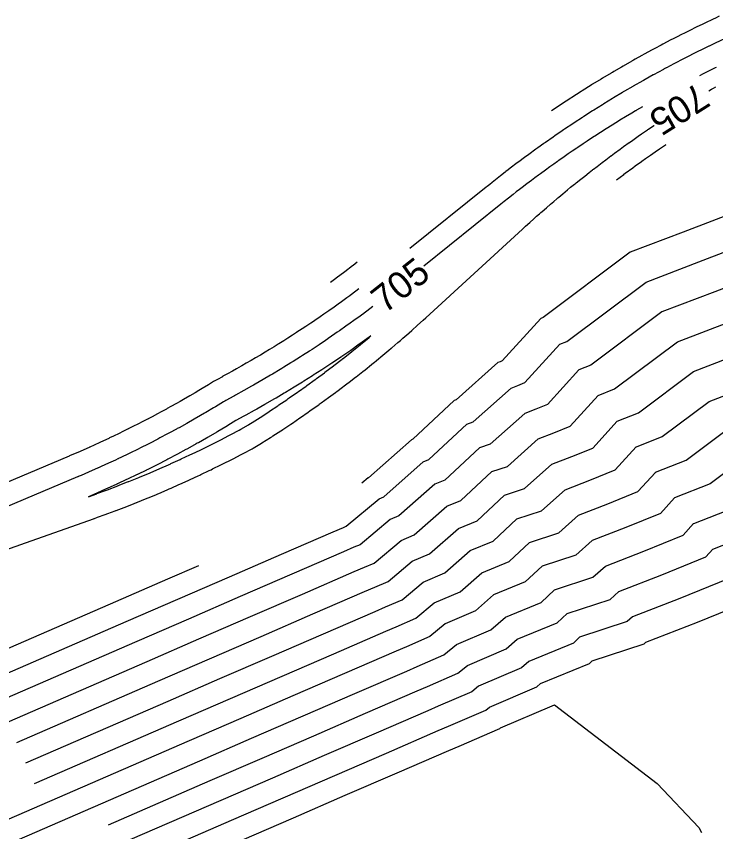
# Model space of a CAD drawing. Extents: x 1487507 to 1489130, y 497211 to 499439.
# Drawn here: x 1487940.5 to 1488002.7, y 498507 to 498579.6 of the extents above; entities that cross this region are included whole.
import ezdxf

# ---------------------------------------------------------------- set-up
doc = ezdxf.new("R2010")
doc.units = 0
for name, color, linetype in [('Prop CMT Ditch DDE', 7, 'Continuous'), ('Prop Drainage Ditch Flow Line', 7, 'Continuous'), ('Prop Drainage Structure Box Number Symbol CELL', 7, 'Continuous')]:
    doc.layers.add(name, color=color, linetype=linetype)

msp = doc.modelspace()

# ---------------------------------------------------------------- linework, layer by layer
at = {"layer": 'Prop CMT Ditch DDE'}
for points in [[(1488003.024, 498579.578), (1488002.689, 498579.423), (1488002.467, 498579.318), (1488001.741, 498578.977), (1488001.609, 498578.913), (1488001.168, 498578.701), (1488001.084, 498578.66), (1488000.798, 498578.521), (1488000.589, 498578.417), (1487999.859, 498578.055), (1487999.722, 498577.986), (1487999.226, 498577.735), (1487999.16, 498577.701), (1487998.924, 498577.58), (1487998.721, 498577.474), (1487997.994, 498577.096), (1487997.841, 498577.014), (1487997.303, 498576.728), (1487997.12, 498576.63), (1487997.069, 498576.602), (1487996.341, 498576.204), (1487996.148, 498576.099), (1487995.548, 498575.763), (1487995.4, 498575.681), (1487995.264, 498575.604), (1487995.232, 498575.586), (1487994.483, 498575.157), (1487994.321, 498575.064), (1487993.649, 498574.67), (1487993.518, 498574.594), (1487993.431, 498574.543), (1487993.415, 498574.533), (1487992.641, 498574.068), (1487992.514, 498573.992), (1487991.761, 498573.531), (1487991.658, 498573.468), (1487991.618, 498573.443), (1487990.813, 498572.937), (1487990.728, 498572.884), (1487989.904, 498572.356), (1487989.842, 498572.316), (1487989.821, 498572.302), (1487988.994, 498571.76), (1487988.963, 498571.74), (1487988.094, 498571.158)], [(1488003.547, 498577.617), (1488002.658, 498577.199), (1488002.111, 498576.936), (1488002.086, 498576.924), (1488001.733, 498576.752), (1488000.821, 498576.301), (1488000.811, 498576.296), (1488000.192, 498575.984), (1488000.189, 498575.982), (1487999.894, 498575.831), (1487998.994, 498575.363), (1487998.982, 498575.356), (1487998.319, 498575.004), (1487998.298, 498574.993), (1487998.073, 498574.873), (1487998.05, 498574.86), (1487997.17, 498574.379), (1487997.141, 498574.364), (1487996.436, 498573.97), (1487996.428, 498573.966), (1487996.271, 498573.877), (1487996.225, 498573.851), (1487995.377, 498573.366), (1487995.326, 498573.336), (1487994.59, 498572.905), (1487994.488, 498572.845), (1487994.418, 498572.803), (1487993.604, 498572.315), (1487993.526, 498572.268), (1487992.764, 498571.801), (1487992.725, 498571.777), (1487992.631, 498571.718), (1487991.851, 498571.229), (1487991.745, 498571.161), (1487990.982, 498570.673), (1487990.961, 498570.659), (1487990.844, 498570.583), (1487990.119, 498570.108), (1487989.985, 498570.018), (1487989.261, 498569.534), (1487989.18, 498569.479), (1487989.045, 498569.386), (1487988.408, 498568.951), (1487988.247, 498568.838), (1487987.562, 498568.359), (1487987.451, 498568.281), (1487987.423, 498568.261), (1487986.87, 498567.866), (1487986.72, 498567.759), (1487986.071, 498567.286), (1487985.885, 498567.15), (1487985.735, 498567.039), (1487985.691, 498567.007), (1487985.204, 498566.644), (1487985.056, 498566.533), (1487984.432, 498566.06), (1487984.232, 498565.907), (1487984.045, 498565.763), (1487983.984, 498565.716), (1487983.559, 498565.385), (1487983.415, 498565.273), (1487982.816, 498564.799), (1487982.604, 498564.631), (1487982.382, 498564.453), (1487982.303, 498564.389), (1487975.491, 498558.91)], [(1487993.881, 498565.033), (1487994.527, 498565.519), (1487994.546, 498565.533), (1487994.655, 498565.613), (1487995.326, 498566.108), (1487995.547, 498566.267), (1487996.113, 498566.675), (1487996.149, 498566.701), (1487996.456, 498566.918), (1487996.905, 498567.235), (1487997.313, 498567.517), (1487997.704, 498567.787), (1487997.795, 498567.849), (1487998.235, 498568.146), (1487998.291, 498568.184)], [(1487923.002, 498513.896), (1487950.265, 498525.735), (1487954.866, 498527.731), (1487959.467, 498529.727), (1487964.069, 498531.72), (1487968.671, 498533.713), (1487969.592, 498534.111), (1487969.829, 498534.214), (1487972.769, 498536.659), (1487973.171, 498536.83), (1487976.69, 498539.939), (1487977.192, 498540.145), (1487980.566, 498543.304), (1487981.132, 498543.491), (1487984.526, 498546.511), (1487985.119, 498546.743), (1487985.73, 498546.99), (1487988.846, 498550.415), (1487989.471, 498550.661), (1487996.509, 498555.935), (1488001.213, 498557.736), (1488005.918, 498559.535)], [(1487968.431, 498555.938), (1487968.913, 498556.29), (1487968.948, 498556.316), (1487968.959, 498556.324), (1487969.703, 498556.879), (1487970.411, 498557.418), (1487970.419, 498557.424), (1487970.451, 498557.449), (1487970.81, 498557.728)], [(1488007.322, 498556.883), (1488002.617, 498555.084), (1487997.913, 498553.283), (1487991.592, 498548.547), (1487990.545, 498548.134), (1487987.741, 498545.052), (1487986.717, 498544.638), (1487985.723, 498544.25), (1487982.654, 498541.518), (1487981.681, 498541.197), (1487978.62, 498538.331), (1487977.734, 498537.967), (1487974.534, 498535.141), (1487973.75, 498534.806), (1487971.072, 498532.579), (1487970.528, 498532.343), (1487969.607, 498531.945), (1487965.004, 498529.953), (1487960.402, 498527.959), (1487955.801, 498525.964), (1487951.201, 498523.967), (1487886.801, 498496.003)], [(1487970.975, 498555.335), (1487970.961, 498555.324), (1487970.691, 498555.123), (1487970.191, 498554.749), (1487970.155, 498554.722), (1487969.885, 498554.525), (1487969.415, 498554.182), (1487969.12, 498553.97), (1487968.635, 498553.623), (1487968.596, 498553.595), (1487968.302, 498553.39), (1487967.849, 498553.072), (1487967.527, 498552.851), (1487967.057, 498552.529), (1487967.016, 498552.501), (1487966.698, 498552.288), (1487966.261, 498551.994), (1487965.913, 498551.765), (1487965.46, 498551.467), (1487965.416, 498551.438), (1487965.074, 498551.219), (1487964.653, 498550.949), (1487964.279, 498550.713), (1487963.842, 498550.438), (1487963.795, 498550.409), (1487963.43, 498550.185), (1487963.026, 498549.936), (1487962.626, 498549.696), (1487962.205, 498549.443), (1487962.156, 498549.413), (1487961.767, 498549.186), (1487961.38, 498548.958), (1487960.954, 498548.714), (1487960.55, 498548.481), (1487960.498, 498548.451), (1487960.087, 498548.221), (1487959.716, 498548.013), (1487959.265, 498547.766), (1487958.877, 498547.553), (1487958.847, 498547.537), (1487958.822, 498547.523), (1487958.394, 498547.283), (1487958.043, 498547.086), (1487957.586, 498546.807), (1487957.227, 498546.589), (1487957.171, 498546.555), (1487956.735, 498546.296), (1487956.405, 498546.099), (1487955.924, 498545.82), (1487955.578, 498545.618), (1487955.519, 498545.585), (1487955.059, 498545.324), (1487954.745, 498545.146), (1487954.249, 498544.87), (1487953.908, 498544.681), (1487953.847, 498544.647), (1487953.386, 498544.397), (1487953.066, 498544.224), (1487952.566, 498543.959), (1487952.22, 498543.776), (1487952.182, 498543.757), (1487952.155, 498543.743), (1487951.69, 498543.502), (1487951.368, 498543.337), (1487950.862, 498543.081), (1487950.512, 498542.905), (1487950.473, 498542.886), (1487950.445, 498542.872), (1487949.977, 498542.642), (1487949.652, 498542.482), (1487949.142, 498542.238), (1487948.787, 498542.068), (1487948.745, 498542.049), (1487948.716, 498542.035), (1487948.248, 498541.816), (1487947.917, 498541.662), (1487947.408, 498541.431), (1487947.043, 498541.265), (1487947.001, 498541.246), (1487946.97, 498541.232), (1487946.505, 498541.026), (1487946.165, 498540.877), (1487945.66, 498540.658), (1487945.283, 498540.497), (1487945.24, 498540.478), (1487945.207, 498540.464), (1487899.403, 498521.123)], [(1487887.737, 498494.235), (1487952.137, 498522.199), (1487956.737, 498524.196), (1487961.338, 498526.191), (1487965.94, 498528.185), (1487970.543, 498530.178), (1487971.463, 498530.576), (1487972.315, 498530.944), (1487974.731, 498532.953), (1487975.898, 498533.452), (1487978.777, 498535.996), (1487980.048, 498536.517), (1487982.797, 498539.09), (1487984.177, 498539.546), (1487986.92, 498541.988), (1487988.315, 498542.533), (1487989.751, 498543.114), (1487992.245, 498545.854), (1487992.248, 498545.855), (1487993.713, 498546.433), (1487999.317, 498550.632), (1488004.02, 498552.433)], [(1487940.538, 498514.989), (1487953.072, 498520.432), (1487957.673, 498522.429), (1487962.274, 498524.424), (1487966.876, 498526.418), (1487971.478, 498528.41), (1487972.399, 498528.808), (1487973.558, 498529.31), (1487975.712, 498531.1), (1487977.261, 498531.763), (1487979.821, 498534.024), (1487981.476, 498534.703), (1487983.912, 498536.984), (1487985.699, 498537.574), (1487988.117, 498539.726), (1487989.914, 498540.428), (1487991.762, 498541.175), (1487993.944, 498543.574), (1487993.948, 498543.575), (1487995.835, 498544.319), (1488000.72, 498547.98), (1488005.424, 498549.781), (1488010.129, 498551.58), (1488011.661, 498552.199)], [(1487942.126, 498511.331), (1487954.944, 498516.897), (1487959.544, 498518.893), (1487964.145, 498520.889), (1487968.747, 498522.882), (1487973.35, 498524.875), (1487974.27, 498525.273), (1487976.045, 498526.04), (1487977.673, 498527.395), (1487979.988, 498528.384), (1487981.908, 498530.081), (1487984.331, 498531.075), (1487986.142, 498532.77), (1487988.744, 498533.63), (1487990.512, 498535.203), (1487993.11, 498536.219), (1487995.784, 498537.299), (1487997.343, 498539.013), (1487997.349, 498539.015), (1488000.077, 498540.091), (1488003.528, 498542.677)], [(1488004.931, 498540.025), (1488002.199, 498537.977), (1487999.049, 498536.735), (1487999.043, 498536.733), (1487997.794, 498535.361), (1487994.708, 498534.114), (1487991.709, 498532.941), (1487990.267, 498531.658), (1487987.257, 498530.664), (1487985.759, 498529.261), (1487982.952, 498528.109), (1487981.351, 498526.695), (1487978.654, 498525.542), (1487977.288, 498524.406), (1487975.206, 498523.505), (1487974.285, 498523.107), (1487969.683, 498521.115), (1487965.081, 498519.121), (1487960.48, 498517.126), (1487955.879, 498515.129), (1487891.48, 498487.165)], [(1487892.416, 498485.397), (1487956.815, 498513.361), (1487961.415, 498515.358), (1487966.017, 498517.353), (1487970.618, 498519.347), (1487975.221, 498521.34), (1487976.142, 498521.738), (1487978.531, 498522.771), (1487979.635, 498523.689), (1487982.714, 498525.006), (1487983.996, 498526.138), (1487987.187, 498527.447), (1487988.373, 498528.557), (1487991.789, 498529.685), (1487992.906, 498530.68), (1487996.306, 498532.009), (1487999.805, 498533.422), (1488000.742, 498534.452), (1488000.749, 498534.455), (1488004.32, 498535.863)], [(1487948.705, 498507.666), (1487957.751, 498511.594), (1487962.351, 498513.591), (1487966.952, 498515.586), (1487971.554, 498517.58), (1487976.157, 498519.572), (1487977.078, 498519.97), (1487979.774, 498521.136), (1487980.616, 498521.836), (1487984.078, 498523.316), (1487985.04, 498524.166), (1487988.615, 498525.633), (1487989.488, 498526.45), (1487993.311, 498527.713), (1487994.103, 498528.418), (1487997.904, 498529.904), (1488001.816, 498531.484), (1488002.442, 498532.172), (1488002.449, 498532.175), (1488006.441, 498533.749)], [(1487950.294, 498504.008), (1487959.622, 498508.059), (1487964.223, 498510.055), (1487968.824, 498512.051), (1487973.426, 498514.044), (1487978.028, 498516.037), (1487978.949, 498516.435), (1487982.26, 498517.867), (1487982.577, 498518.13), (1487986.804, 498519.938), (1487987.127, 498520.223), (1487991.471, 498522.005), (1487991.718, 498522.237), (1487996.356, 498523.769), (1487996.498, 498523.895), (1488001.101, 498525.694), (1488005.837, 498527.608)], [(1487960.558, 498506.291), (1487965.158, 498508.288), (1487969.759, 498510.283), (1487974.361, 498512.277), (1487978.964, 498514.269), (1487979.885, 498514.667), (1487983.504, 498516.232), (1487983.558, 498516.278), (1487988.168, 498518.248), (1487988.171, 498518.251), (1487988.38, 498518.337), (1487997.496, 498511.322), (1488001.207, 498507.427), (1488001.441, 498506.985)]]:
    msp.add_lwpolyline(points, dxfattribs=at)
msp.add_lwpolyline([(1487971.066, 498550.345), (1487971.105, 498550.377), (1487971.876, 498551.01), (1487971.88, 498551.014), (1487972.041, 498551.149), (1487971.869, 498551.023), (1487971.867, 498551.022), (1487971.057, 498550.439), (1487971.017, 498550.411), (1487971.005, 498550.403), (1487970.239, 498549.864), (1487969.445, 498549.318), (1487969.415, 498549.298), (1487969.372, 498549.268), (1487968.624, 498548.764), (1487968.587, 498548.739), (1487968.546, 498548.713), (1487967.752, 498548.189), (1487967.707, 498548.16), (1487967.659, 498548.129), (1487966.913, 498547.648), (1487966.853, 498547.61), (1487966.069, 498547.115), (1487966.02, 498547.085), (1487965.953, 498547.044), (1487965.219, 498546.591), (1487964.453, 498546.129), (1487964.365, 498546.076), (1487964.314, 498546.046), (1487963.599, 498545.624), (1487963.506, 498545.57), (1487963.405, 498545.511), (1487962.642, 498545.072), (1487962.588, 498545.041), (1487961.885, 498544.646), (1487961.774, 498544.583), (1487961.651, 498544.516), (1487960.9, 498544.103), (1487960.843, 498544.072), (1487960.72, 498544.003), (1487960.032, 498543.615), (1487959.305, 498543.174), (1487959.181, 498543.098), (1487959.122, 498543.063), (1487958.432, 498542.654), (1487958.324, 498542.59), (1487957.569, 498542.152), (1487957.461, 498542.09), (1487957.4, 498542.055), (1487956.686, 498541.65), (1487956.594, 498541.598), (1487956.497, 498541.544), (1487955.721, 498541.115), (1487955.657, 498541.08), (1487955.575, 498541.036), (1487954.844, 498540.641), (1487954.763, 498540.599), (1487953.961, 498540.175), (1487953.894, 498540.14), (1487953.828, 498540.106), (1487953.074, 498539.718), (1487953.011, 498539.687), (1487952.181, 498539.27), (1487952.111, 498539.235), (1487952.062, 498539.211), (1487951.284, 498538.831), (1487951.24, 498538.809), (1487950.383, 498538.4), (1487950.309, 498538.366), (1487949.501, 498537.99), (1487949.476, 498537.979), (1487949.45, 498537.967), (1487948.566, 498537.566), (1487948.489, 498537.532), (1487947.658, 498537.166), (1487947.643, 498537.159), (1487946.91, 498536.845), (1487947.66, 498537.115), (1487947.669, 498537.118), (1487948.512, 498537.43), (1487948.53, 498537.437), (1487948.607, 498537.466), (1487949.513, 498537.813), (1487949.542, 498537.824), (1487949.569, 498537.834), (1487950.398, 498538.161), (1487950.474, 498538.191), (1487950.513, 498538.207), (1487951.402, 498538.568), (1487951.447, 498538.587), (1487952.254, 498538.923), (1487952.327, 498538.954), (1487952.386, 498538.979), (1487953.248, 498539.349), (1487954.024, 498539.691), (1487954.095, 498539.723), (1487954.165, 498539.754), (1487954.244, 498539.79), (1487955.078, 498540.168), (1487955.161, 498540.206), (1487955.921, 498540.56), (1487955.988, 498540.591), (1487956.087, 498540.638), (1487956.894, 498541.023), (1487957.625, 498541.381), (1487957.731, 498541.433), (1487957.795, 498541.465), (1487958.568, 498541.853), (1487958.692, 498541.916), (1487959.401, 498542.28), (1487959.525, 498542.344), (1487959.585, 498542.376), (1487960.331, 498542.769), (1487960.474, 498542.845), (1487961.152, 498543.249), (1487961.28, 498543.325), (1487961.336, 498543.36), (1487961.468, 498543.444), (1487962.183, 498543.901), (1487962.864, 498544.345), (1487962.972, 498544.414), (1487963.024, 498544.449), (1487963.757, 498544.937), (1487963.86, 498545.006), (1487964.552, 498545.477), (1487964.64, 498545.537), (1487964.689, 498545.571), (1487964.779, 498545.633), (1487965.513, 498546.144), (1487965.588, 498546.197), (1487966.284, 498546.691), (1487966.33, 498546.725), (1487967.081, 498547.27), (1487967.142, 498547.314), (1487967.198, 498547.355), (1487967.903, 498547.878), (1487967.947, 498547.911), (1487968.705, 498548.485), (1487968.746, 498548.516), (1487969.468, 498549.073), (1487969.498, 498549.096), (1487969.539, 498549.128), (1487969.569, 498549.152), (1487970.325, 498549.749), (1487970.344, 498549.764)], close=True, dxfattribs=at)
at = {"layer": 'Prop Drainage Ditch Flow Line'}
for points in [[(1488047.838, 498579.27), (1488037.202, 498575.248), (1488032.489, 498573.464), (1488027.776, 498571.679), (1488023.066, 498569.891), (1488018.356, 498568.101), (1488013.657, 498566.289), (1488009.175, 498564.069), (1488004.514, 498562.187), (1487999.809, 498560.388), (1487995.105, 498558.587), (1487987.349, 498552.775), (1487987.146, 498552.695), (1487983.719, 498548.928), (1487983.521, 498548.848), (1487983.328, 498548.773), (1487979.609, 498545.463), (1487979.451, 498545.41), (1487975.764, 498541.959), (1487975.646, 498541.911), (1487971.808, 498538.52), (1487971.788, 498538.511), (1487971.225, 498538.043)], [(1488002.762, 498575.031), (1488002.667, 498574.984), (1488002.422, 498574.863), (1488001.764, 498574.538), (1488001.592, 498574.451), (1488001.254, 498574.281)], [(1488002.095, 498572.949), (1488002.339, 498573.093), (1488002.496, 498573.185), (1488002.724, 498573.318)], [(1487996.184, 498571.522), (1487995.937, 498571.377), (1487995.661, 498571.216), (1487995.597, 498571.179), (1487995.561, 498571.157), (1487995.243, 498570.967), (1487994.694, 498570.638), (1487994.184, 498570.327), (1487993.87, 498570.135), (1487993.831, 498570.111), (1487993.497, 498569.901), (1487992.974, 498569.574), (1487992.466, 498569.25), (1487992.122, 498569.029), (1487992.101, 498569.016), (1487991.759, 498568.792), (1487991.275, 498568.476), (1487990.916, 498568.236), (1487990.433, 498567.913), (1487990.388, 498567.883), (1487990.354, 498567.86), (1487989.93, 498567.57), (1487989.597, 498567.342), (1487989.224, 498567.081), (1487988.766, 498566.763), (1487988.692, 498566.711), (1487988.63, 498566.667), (1487988.312, 498566.439), (1487987.941, 498566.175), (1487987.553, 498565.892), (1487987.121, 498565.578), (1487987.022, 498565.505), (1487986.931, 498565.438), (1487986.628, 498565.212), (1487986.307, 498564.973), (1487985.906, 498564.669), (1487985.5, 498564.36), (1487985.379, 498564.267), (1487985.256, 498564.173), (1487984.971, 498563.951), (1487984.698, 498563.739), (1487984.284, 498563.411), (1487983.902, 498563.109), (1487983.746, 498562.984), (1487983.607, 498562.873), (1487976.732, 498557.343)], [(1487902.07, 498518.884), (1487947.368, 498534.885), (1487947.428, 498534.906), (1487947.451, 498534.915), (1487947.719, 498535.011), (1487948.411, 498535.261), (1487948.647, 498535.348), (1487949.288, 498535.586), (1487949.347, 498535.609), (1487949.368, 498535.616), (1487949.614, 498535.711), (1487950.322, 498535.982), (1487950.982, 498536.243), (1487951.194, 498536.326), (1487951.213, 498536.334), (1487951.272, 498536.357), (1487951.999, 498536.653), (1487952.218, 498536.742), (1487952.894, 498537.024), (1487953.087, 498537.105), (1487953.161, 498537.136), (1487953.902, 498537.455), (1487954.1, 498537.54), (1487954.278, 498537.618), (1487954.965, 498537.921), (1487955.036, 498537.953), (1487955.791, 498538.296), (1487955.967, 498538.376), (1487956.672, 498538.705), (1487956.827, 498538.776), (1487956.895, 498538.808), (1487957.663, 498539.176), (1487957.818, 498539.25), (1487957.958, 498539.319), (1487958.672, 498539.669), (1487958.737, 498539.701), (1487958.878, 498539.771), (1487959.652, 498540.161), (1487959.774, 498540.224), (1487960.501, 498540.598), (1487960.562, 498540.631), (1487960.683, 498540.694), (1487961.468, 498541.109), (1487961.571, 498541.17), (1487962.291, 498541.599), (1487962.348, 498541.635), (1487963.092, 498542.109), (1487963.212, 498542.186), (1487963.326, 498542.26), (1487964.017, 498542.709), (1487964.07, 498542.744), (1487964.201, 498542.832), (1487964.923, 498543.312), (1487965.054, 498543.401), (1487965.719, 498543.853), (1487965.769, 498543.888), (1487966.455, 498544.364), (1487966.61, 498544.472), (1487967.243, 498544.921), (1487967.396, 498545.029), (1487967.444, 498545.064), (1487967.609, 498545.184), (1487968.272, 498545.664), (1487968.88, 498546.114), (1487969.049, 498546.239), (1487969.094, 498546.272), (1487969.275, 498546.41), (1487969.909, 498546.889), (1487970.089, 498547.027), (1487970.676, 498547.48), (1487970.718, 498547.513), (1487971.318, 498547.986), (1487971.52, 498548.145), (1487972.078, 498548.593), (1487972.277, 498548.753), (1487972.316, 498548.785), (1487972.528, 498548.96), (1487973.105, 498549.433), (1487973.638, 498549.879), (1487973.851, 498550.057), (1487973.887, 498550.088), (1487974.432, 498550.554), (1487974.662, 498550.751), (1487974.886, 498550.946), (1487975.397, 498551.392), (1487975.431, 498551.421), (1487975.671, 498551.635), (1487976.192, 498552.099), (1487976.676, 498552.538), (1487976.915, 498552.756), (1487985.517, 498560.65), (1487985.656, 498560.778), (1487985.788, 498560.898), (1487986.158, 498561.233), (1487986.52, 498561.559), (1487986.775, 498561.786), (1487987.034, 498562.015), (1487987.144, 498562.112), (1487987.259, 498562.213), (1487987.644, 498562.547), (1487988.004, 498562.859), (1487988.308, 498563.118), (1487988.58, 498563.35), (1487988.662, 498563.419), (1487988.756, 498563.498), (1487989.105, 498563.789), (1487989.515, 498564.13), (1487989.803, 498564.365), (1487990.155, 498564.653), (1487990.225, 498564.709), (1487990.281, 498564.755), (1487990.716, 498565.102), (1487991.053, 498565.371), (1487991.458, 498565.689), (1487991.757, 498565.924), (1487991.788, 498565.948), (1487991.831, 498565.981), (1487992.156, 498566.23), (1487992.615, 498566.583), (1487992.926, 498566.816), (1487993.387, 498567.162), (1487993.406, 498567.177), (1487993.718, 498567.406), (1487994.203, 498567.763), (1487994.508, 498567.983), (1487995.006, 498568.341), (1487995.043, 498568.367), (1487995.327, 498568.568), (1487995.816, 498568.912), (1487996.106, 498569.113), (1487996.631, 498569.474), (1487996.663, 498569.497), (1487996.724, 498569.538), (1487997.203, 498569.861), (1487997.224, 498569.875)], [(1487972.216, 498553.767), (1487971.672, 498553.361), (1487971.433, 498553.182), (1487971.397, 498553.155), (1487970.863, 498552.764), (1487970.642, 498552.602), (1487970.069, 498552.191), (1487969.846, 498552.031), (1487969.806, 498552.003), (1487969.248, 498551.612), (1487969.044, 498551.468), (1487968.832, 498551.322), (1487968.236, 498550.913), (1487968.194, 498550.884), (1487968.001, 498550.755), (1487967.424, 498550.366), (1487966.796, 498549.954), (1487966.606, 498549.828), (1487966.561, 498549.799), (1487965.955, 498549.409), (1487965.783, 498549.298), (1487965.128, 498548.886), (1487964.955, 498548.777), (1487964.908, 498548.747), (1487964.277, 498548.359), (1487964.123, 498548.264), (1487963.962, 498548.167), (1487963.285, 498547.76), (1487963.235, 498547.729), (1487963.092, 498547.645), (1487962.443, 498547.264), (1487961.732, 498546.855), (1487961.596, 498546.776), (1487961.543, 498546.746), (1487961.418, 498546.676), (1487960.745, 498546.298), (1487960.006, 498545.892), (1487959.889, 498545.828), (1487959.832, 498545.798), (1487959.142, 498545.409), (1487959.038, 498545.35), (1487958.928, 498545.284), (1487958.204, 498544.843), (1487958.147, 498544.809), (1487958.034, 498544.743), (1487957.364, 498544.345), (1487957.234, 498544.269), (1487956.519, 498543.854), (1487956.459, 498543.82), (1487956.329, 498543.746), (1487955.67, 498543.372), (1487954.971, 498542.985), (1487954.815, 498542.898), (1487954.752, 498542.864), (1487954.11, 498542.516), (1487953.955, 498542.433), (1487953.267, 498542.069), (1487953.09, 498541.976), (1487953.024, 498541.941), (1487952.394, 498541.617), (1487952.221, 498541.528), (1487951.544, 498541.187), (1487951.347, 498541.088), (1487951.278, 498541.053), (1487950.66, 498540.751), (1487950.468, 498540.657), (1487949.803, 498540.339), (1487949.585, 498540.234), (1487949.566, 498540.226), (1487949.512, 498540.2), (1487949.306, 498540.104), (1487948.697, 498539.821), (1487948.045, 498539.524), (1487947.805, 498539.416), (1487947.784, 498539.406), (1487947.729, 498539.382), (1487947.503, 498539.282), (1487946.908, 498539.02), (1487946.269, 498538.745), (1487946.007, 498538.632), (1487945.984, 498538.623), (1487945.929, 498538.599), (1487901.687, 498519.918)], [(1487941.332, 498513.16), (1487954.008, 498518.664), (1487958.608, 498520.661), (1487963.209, 498522.656), (1487967.811, 498524.65), (1487972.414, 498526.642), (1487973.335, 498527.041), (1487974.802, 498527.675), (1487976.692, 498529.247), (1487978.624, 498530.073), (1487980.865, 498532.053), (1487982.904, 498532.889), (1487985.027, 498534.877), (1487987.222, 498535.602), (1487989.314, 498537.465), (1487991.512, 498538.323), (1487993.773, 498539.237), (1487995.644, 498541.293), (1487995.648, 498541.295), (1487997.956, 498542.205), (1488002.124, 498545.328), (1488006.828, 498547.129), (1488011.533, 498548.928), (1488012.828, 498549.451)], [(1487956.687, 498530.695), (1487953.93, 498529.499), (1487949.329, 498527.502), (1487922.207, 498515.725)], [(1488003.827, 498529.546), (1487999.503, 498527.799), (1487995.301, 498526.157), (1487994.834, 498525.741), (1487990.603, 498524.344), (1487990.043, 498523.819), (1487986.083, 498522.195), (1487985.441, 498521.627), (1487981.596, 498519.983), (1487981.017, 498519.502), (1487978.013, 498518.203), (1487977.093, 498517.804), (1487972.49, 498515.812), (1487967.888, 498513.818), (1487963.287, 498511.823), (1487958.686, 498509.826), (1487949.499, 498505.837)]]:
    msp.add_lwpolyline(points, dxfattribs=at)

# ---------------------------------------------------------------- texts
at = {"layer": 'Prop Drainage Structure Box Number Symbol CELL'}
for rotation, p in [(212.25431, (1488001.106, 498573.744)), (38.36772, (1487973.283, 498553.082))]:
    msp.add_text('705', height=2.4, rotation=rotation, dxfattribs=at).set_placement(p)

doc.saveas('drawing.dxf')
